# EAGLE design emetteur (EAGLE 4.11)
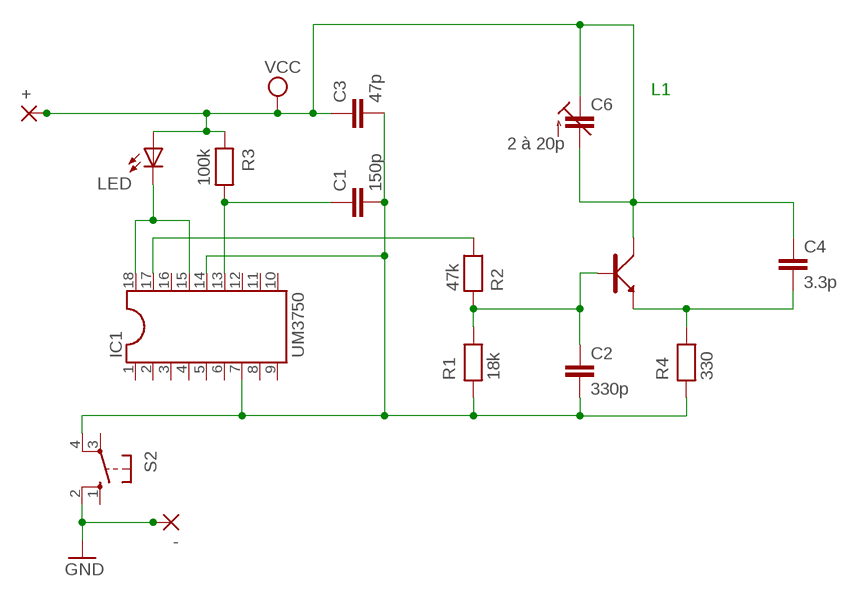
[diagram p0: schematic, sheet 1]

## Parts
2SC2570  2sc2570  2SC2570  [NPN7F]
+  2,54/1,1  [2,54/1,1]
-  2,54/1,1  [2,54/1,1]
C1  150p  C-EU050-025X075  [C050-025X075]
C2  330p  C-EU050-025X075  [C050-025X075]
C3  47p  C-EU050-025X075  [C050-025X075]
C4  3.3p  C-EU050-025X075  [C050-025X075]
C6  2 à 20p  C-TRIMM808-1  [CTRIM808-1]
IC1  UM3750  DIL18  [DIL18]
LED  LED3MM  [LED3MM]
R1  18k  RESEU-10  [R-10]
R2  47k  RESEU-10  [R-10]
R3  100k  RESEU-10  [R-10]
R4  330  RESEU-10  [R-10]
S2  10-XX  [MANU]

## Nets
GND: -.1(P) S2.2(S1)
N$1: 2SC2570.P$3 C2.1 R1.2 R2.1
N$2: IC1.17 R2.2
N$3: C1.1 IC1.13 R3.2
N$5: IC1.15 IC1.18 LED.K(C)
N$7: C1.2 C2.2 C3.2 IC1.7 IC1.14 R1.1 R4.1 S2.4(P1)
N$10: 2SC2570.P$2 C4.2 R4.2
VCC: 2SC2570.P$1 +.1(P) C3.1 C4.1 C6.1(E) C6.2(A) LED.A R3.1
Unconnected: IC1.1 IC1.2 IC1.3 IC1.4 IC1.5 IC1.6 IC1.8 IC1.9 IC1.10 IC1.11 IC1.12 IC1.16 S2.1(S) S2.3(P)

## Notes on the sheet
- L1

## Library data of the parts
2SC2570 = manu:2SC2570: NPN transistor
+ - = wirepad:2,54/1,1: THROUGH-HOLE PAD
C1-C4 = rcl:C-EU: CAPACITOR, European symbol
C6 = rcl:C-TRIMM: Trimm capacitor
IC1 = dil:DIL18: SOCKET Dual In Line
LED = led:LED: LED
R1-R4 = discrete:RESEU-10
S2 = switch-omron:10-XX: OMRON SWITCH

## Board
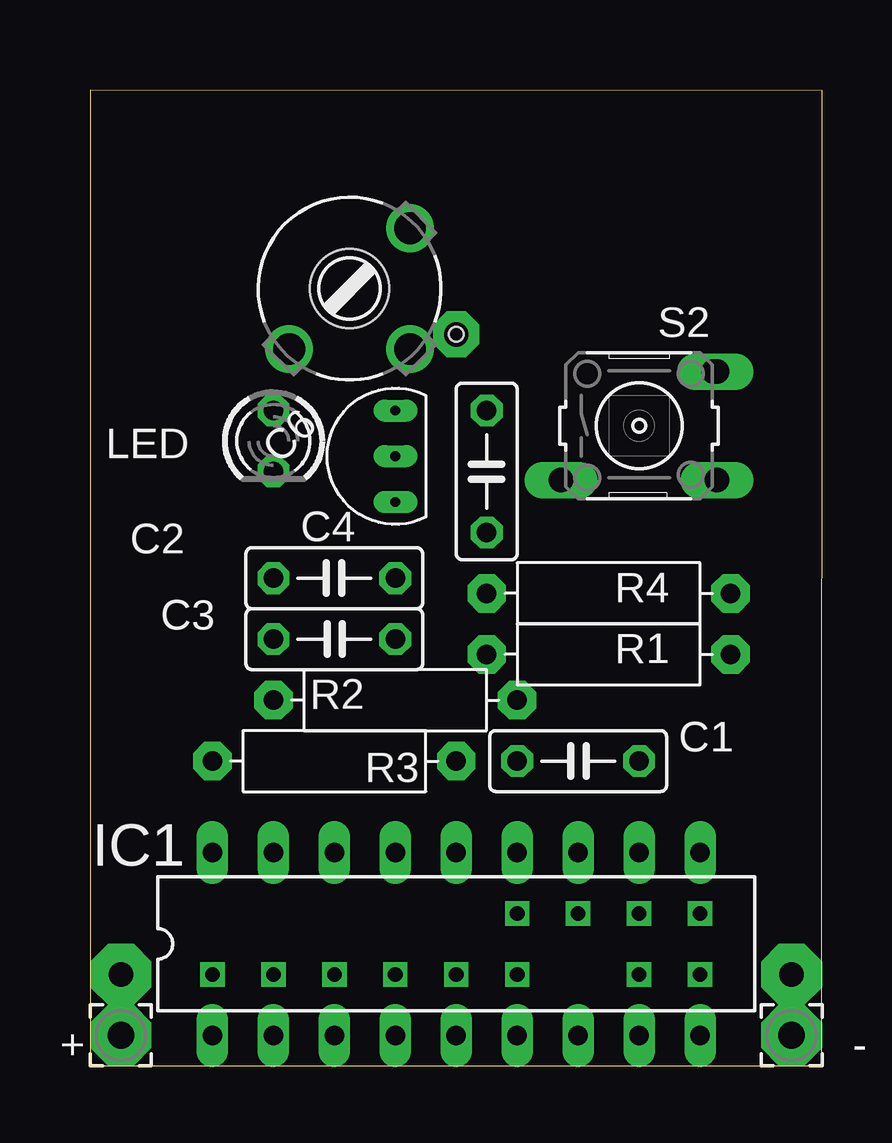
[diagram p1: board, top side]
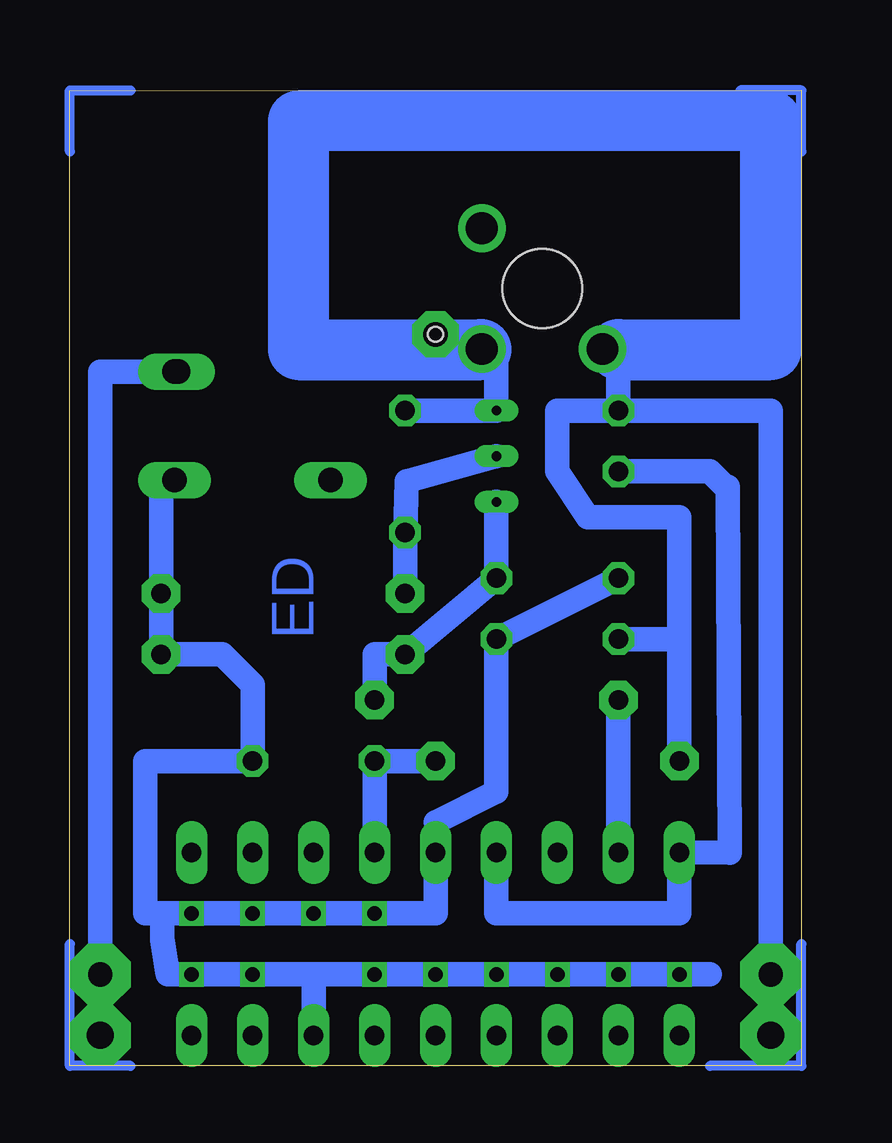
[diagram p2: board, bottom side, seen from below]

Size 30.48 x 40.64 mm. Coordinates in mm from the lower left corner, seen from the top.
Outline: 0,0 30.48,0 30.48,40.64 0,40.64 0,0
Copper layers 16: Bottom 0.035mm
Design rules "default": minimum track width 20mil, minimum drill 24mil, track to track 8mil, track to pad 8mil, pad to pad 8mil, via to via 8mil, smd to smd 8mil, copper to edge 40mil, drill to drill 8mil, minimum pad ring 10mil, minimum via ring 8mil, stop-mask expansion 4mil, vias tented up to drill 0mil, thermal gap 10mil
Holes 0.61 mm at 15.24,30.48

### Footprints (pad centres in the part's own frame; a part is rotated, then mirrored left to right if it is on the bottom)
NPN7F = drill 0.406 long: P$1 0,1.905; P$2 0,0; P$3 0,-1.905
2,54/1,1 = drill 1.118 pad 2.54 octagon: 1 0,0
C050-025X075 = drill 0.813 octagon: 1 -2.54,0; 2 2.54,0
CTRIM808-1 = drill 1.321 round: 1 -3.556,0; 2 0,-3.556; 3 3.556,0 | hole 3.302: 0,0
DIL18 = drill 0.813 long: 1 -10.16,-3.81; 2 -7.62,-3.81; 3 -5.08,-3.81; 4 -2.54,-3.81; 5 0,-3.81; 6 2.54,-3.81; 7 5.08,-3.81; 8 7.62,-3.81; 9 10.16,-3.81; 10 10.16,3.81; 11 7.62,3.81; 12 5.08,3.81; 13 2.54,3.81; 14 0,3.81; 15 -2.54,3.81; 16 -5.08,3.81; 17 -7.62,3.81; 18 -10.16,3.81
LED3MM = drill 0.813 octagon: A -1.27,0; K 1.27,0
R-10 = drill 0.813 pad 1.6 octagon: 1 -5.08,0; 2 5.08,0
MANU = drill 1.016 long: 1 3.099,2.261; 2 3.251,2.261; 3 -3.251,-2.261; 4 3.251,-2.261

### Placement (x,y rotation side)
2SC2570  12.7,25.4 0 top
+  1.27,1.27 0 top
-  29.21,1.27 0 top
C1  20.32,12.7 0 top
C2  10.16,20.32 180 top
C3  10.16,17.78 0 top
C4  16.51,24.77 270 top
C6  10.79,32.39 45 top
IC1  15.24,5.08 0 top
LED  7.62,26.04 270 top
R1  21.59,17.15 180 top
R2  12.7,15.24 180 top
R3  10.16,12.7 0 top
R4  21.59,19.69 180 top
S2  22.86,26.67 0 top

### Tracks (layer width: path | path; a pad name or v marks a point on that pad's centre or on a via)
GND  (via drill 1.02 pad 2.54)
  Bottom 0.406: 29.21,27.94 28.93,25.68
  Bottom 1.016: -.1 v29.21,3.81 29.21,27.94 29.21,28.93 S2.2
N$1
  Bottom 1.016: R2.1 17.78,17.15 R1.2 C2.1 2SC2570.P$3
N$2
  Bottom 1.016: IC1.17 R2.2
N$3
  Bottom 1.016: IC1.13 C1.1 R3.2
N$4
  Bottom 0.406: 0,5.08 0,0 3.81,0
N$5
  Bottom 1.016: IC1.15 12.7,6.35 5.08,6.35 IC1.18 2.98,8.89 3.07,24.13 3.07,24.03 3.81,24.77 LED.K
N$6
  Bottom 0.406: 27.94,0 30.48,0 30.48,5.08
N$7  (via drill 0.61)
  Bottom 0.406: IC1.14 15.24,10.16 | v15.24,3.81 v17.78,3.81 20.32,3.81 v22.86,3.81 v25.4,3.81
  Bottom 1.016: C2.2 C3.2 12.7,11.43 15.24,10.16 | 20.32,3.81 IC1.7 | 3.81,3.81 v5.08,3.81 v7.62,3.81 v10.16,3.81 v12.7,3.81 v15.24,3.81 v17.78,3.81 v22.86,3.81 v25.4,3.81 26.41,3.81 26.62,5.27 26.62,6.35 27.33,6.35 | 27.33,6.35 27.33,12.7 C1.2 22.86,15.88 24.13,17.15 R1.1 R4.1 26.67,24.41 S2.4 | IC1.14 15.24,6.35 v17.78,6.35 v20.32,6.35 v22.86,6.35 v25.4,6.35 27.33,6.35
N$8
  Bottom 0.406: 2.54,40.64 0,40.64 0,38.1
N$9
  Bottom 0.406: 27.94,40.64 30.48,40.64 30.48,38.1
N$10
  Bottom 1.016: R4.2 C4.2 16.44,24.36 2SC2570.P$2
N$11  (via drill 1.02 pad 1.93)
  other vias: 15.24,30.48
VCC  (via drill 1.02 pad 2.54)
  Bottom 0.406: +.1 v1.27,3.81
  Bottom 1.016: 5.08,17.78 R3.1 | 5.08,17.78 C3.1 | 5.08,17.78 5.08,22.86 8.89,22.86 10.16,24.77 10.16,27.31 LED.A | v1.27,3.81 1.27,27.31 LED.A | C4.1 2SC2570.P$1 12.7,29.21 13.33,29.85 C6.2 | LED.A 7.62,29.21 8.25,29.85 | 8.25,29.85 C6.1 | 8.25,29.85 7.62,29.85
  Bottom 2.54: 13.33,29.85 20.95,29.85 20.95,39.37 1.27,39.37 1.27,29.85 7.62,29.85

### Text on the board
Bottom: ED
